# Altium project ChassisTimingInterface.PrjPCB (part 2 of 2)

## Sheet ChassisTimingInterface5.SchDoc
size C; SheetNumber: 5; SheetTotal: 6
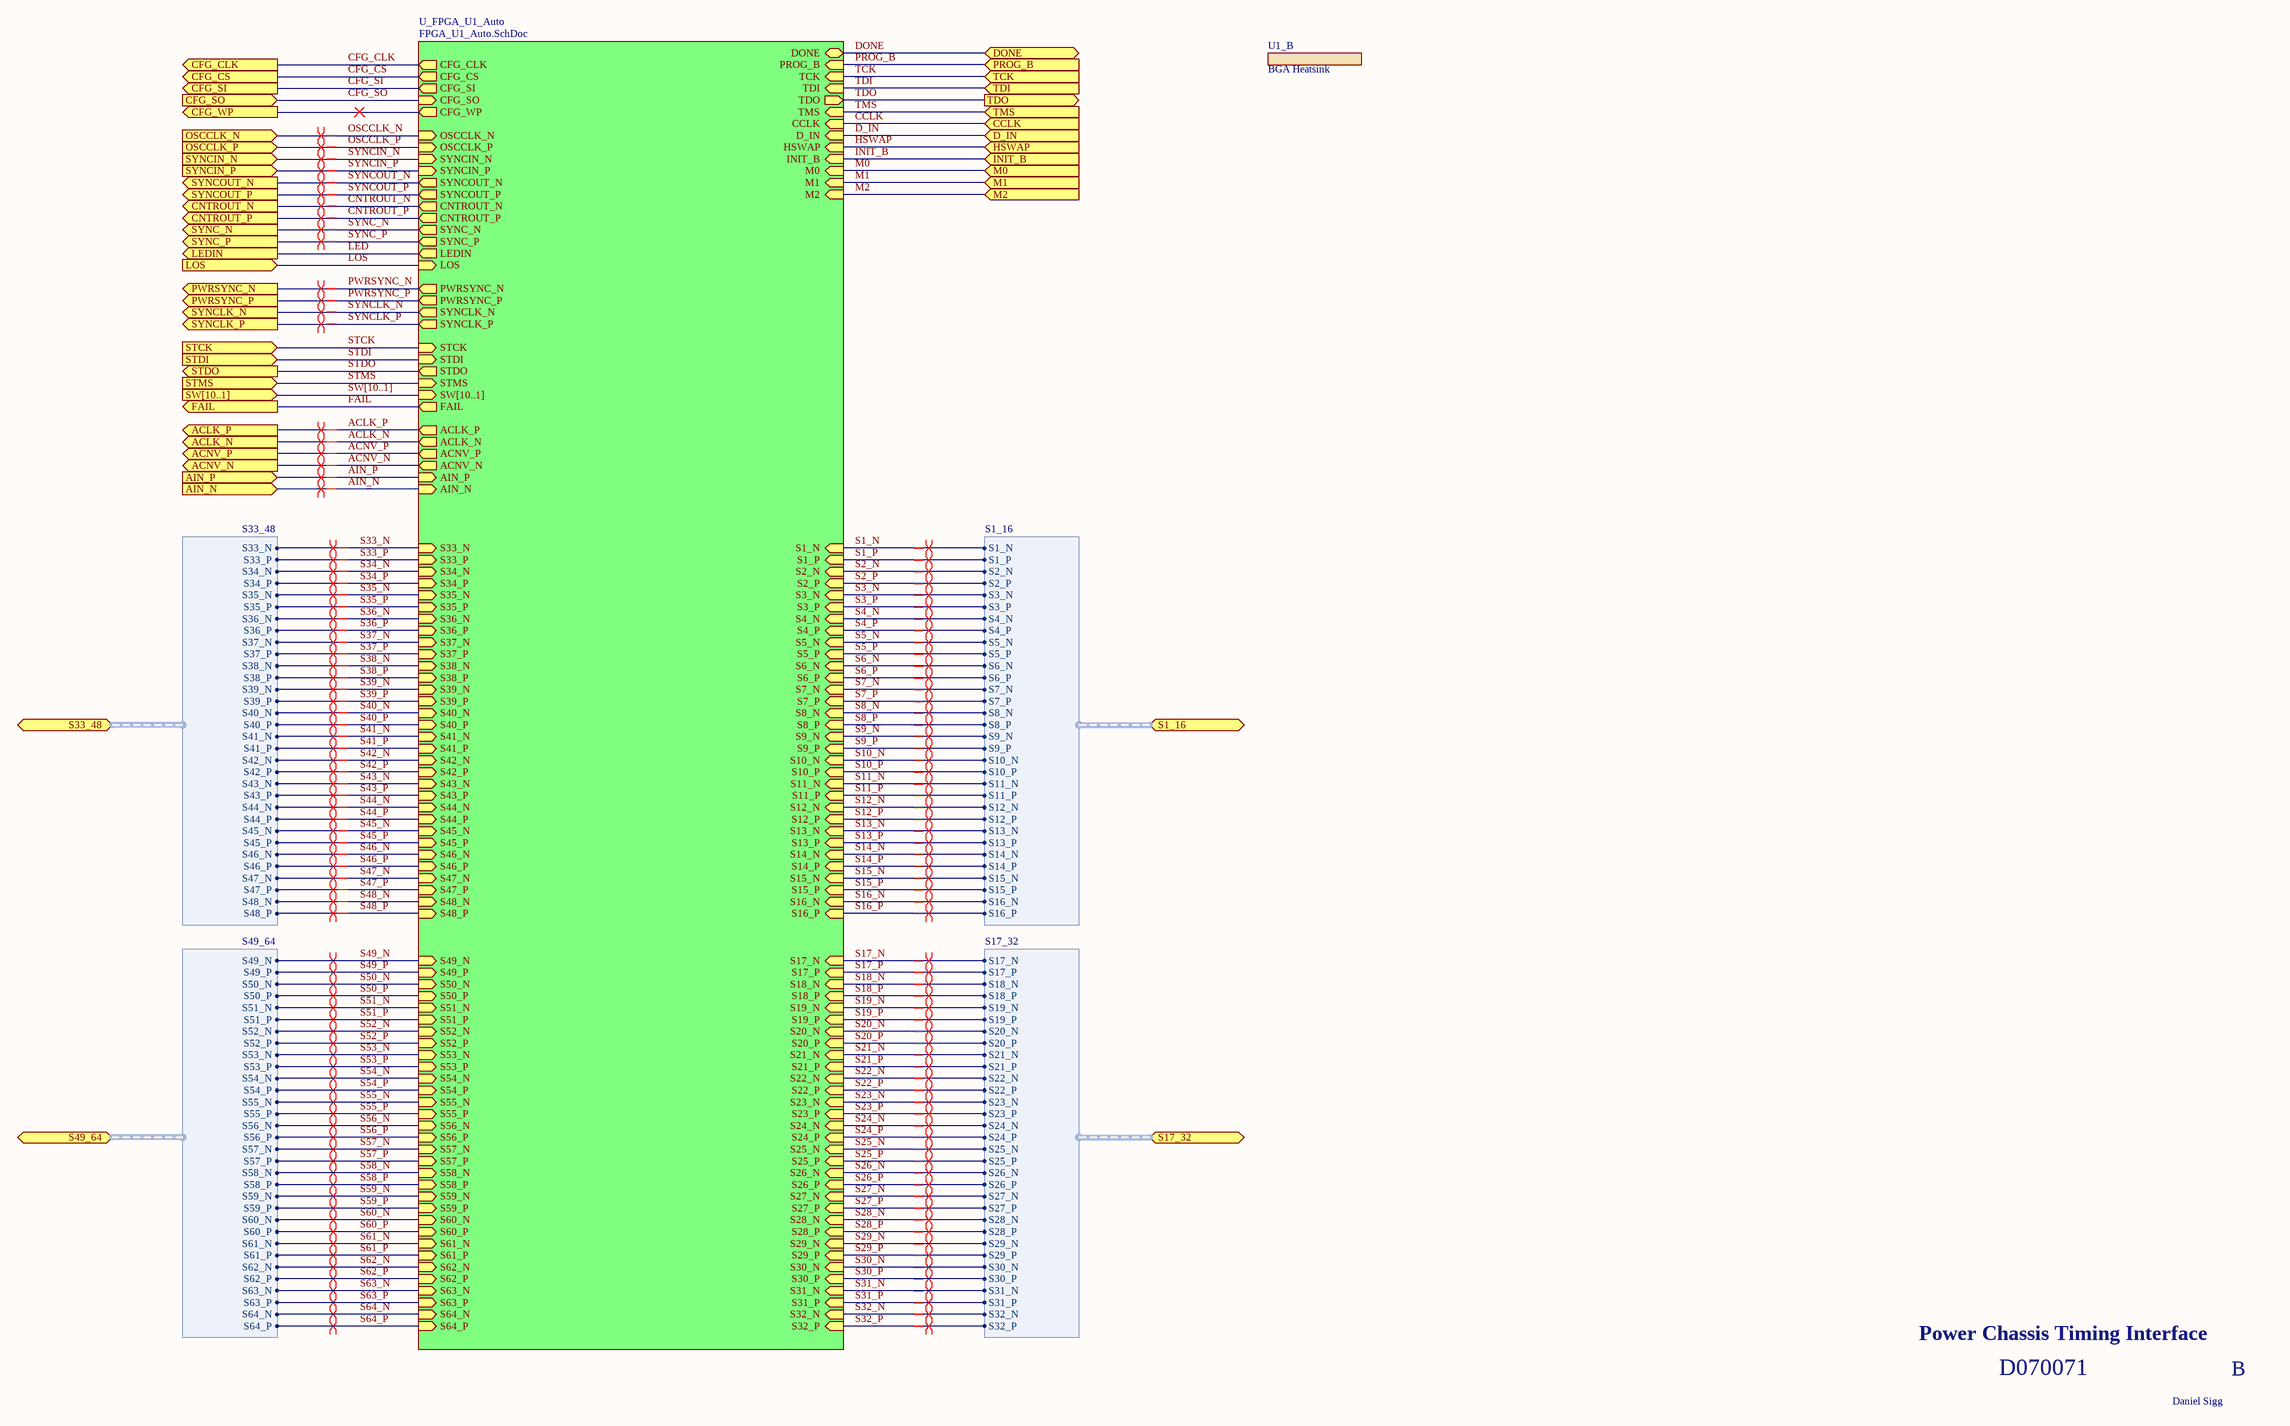
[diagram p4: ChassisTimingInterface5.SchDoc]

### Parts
U1_B  BGA Heatsink  (mechanical)

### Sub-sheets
U_FPGA_U1_Auto = FPGA_U1_Auto.SchDoc: CCLK (in), CFG_CLK (out), CFG_CS (out), CFG_SI (out), CFG_SO (in), CFG_WP (out), CNTROUT_N (out), CNTROUT_P (out), D_IN (in), HSWAP (in), INIT_B (in), LEDIN (out), LOS (in), M0 (in), M1 (in), M2 (in), OSCCLK_N (in), OSCCLK_P (in), PWRSYNC_N (out), PWRSYNC_P (out), S1_N (in), S1_P (in), S2_N (in), S2_P (in), S3_N (in), S3_P (in), S4_N (in), S4_P (in), S5_N (in), S5_P (in), S6_N (in), S6_P (in), S7_N (in), S7_P (in), S8_N (in), S8_P (in), STCK (in), STDI (in), STDO (out), STMS (in), SW[10..1] (in), SYNC_N (out), SYNC_P (out), SYNCIN_N (in), SYNCIN_P (in), SYNCLK_N (out), SYNCLK_P (out), SYNCOUT_N (out), SYNCOUT_P (out), DONE (bidir), PROG_B (in), TCK (in), TDI (in), TDO (out), TMS (in), FAIL (out), S9_P (in), S9_N (in), S10_P (in), S10_N (in), S11_P (in), S11_N (in), S12_P (in), S12_N (in), S13_P (in), S13_N (in), S14_P (in), S14_N (in), S15_P (in), S15_N (in), S16_P (in), S16_N (in), ACLK_N (out), ACLK_P (out), ACNV_N (out), ACNV_P (out), AIN_N (in), AIN_P (in), S17_N (in), S17_P (in), S18_N (in), S18_P (in), S19_N (in), S19_P (in), S20_N (in), S20_P (in), S21_N (in), S21_P (in), S22_N (in), S22_P (in), S23_N (in), S23_P (in), S24_N (in), S24_P (in), S25_N (in), S25_P (in), S26_N (in), S26_P (in), S27_N (in), S27_P (in), S28_N (in), S28_P (in), S29_N (in), S29_P (in), S30_N (in), S30_P (in), S31_N (in), S31_P (in), S32_N (in), S32_P (in), S33_N (in), S33_P (in), S34_N (in), S34_P (in), S35_N (in), S35_P (in), S36_N (in), S36_P (in), S37_N (in), S37_P (in), S38_N (in), S38_P (in), S39_N (in), S39_P (in), S40_N (in), S40_P (in), S49_N (in), S49_P (in), S50_N (in), S50_P (in), S51_N (in), S51_P (in), S52_N (in), S52_P (in), S53_N (in), S53_P (in), S54_N (in), S54_P (in), S55_N (in), S55_P (in), S56_N (in), S56_P (in), S57_N (in), S57_P (in), S58_N (in), S58_P (in), S59_N (in), S59_P (in), S60_N (in), S60_P (in), S61_N (in), S61_P (in), S62_N (in), S62_P (in), S63_N (in), S63_P (in), S64_N (in), S64_P (in), S42_N (in), S41_P (in), S42_P (in), S43_N (in), S43_P (in), S44_N (in), S44_P (in), S45_N (in), S45_P (in), S46_N (in), S46_P (in), S47_N (in), S47_P (in), S48_N (in), S48_P (in), S41_N (in)

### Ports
ACLK_N (out), ACLK_P (out), ACNV_N (out), ACNV_P (out), AIN_N (in), AIN_P (in), CCLK (in), CFG_CLK (out), CFG_CS (out), CFG_SI (out), CFG_SO (in), CFG_WP (out), CNTROUT_N (out), CNTROUT_P (out), D_IN (in), DONE (bidir), FAIL (out), HSWAP (in), INIT_B (in), LEDIN (out), LOS (in), M0 (in), M1 (in), M2 (in), OSCCLK_N (in), OSCCLK_P (in), PROG_B (in), PWRSYNC_N (out), PWRSYNC_P (out), S1_16 (harness S1_16), S17_32 (harness S17_32), S33_48 (harness S33_48), S49_64 (harness S49_64), STCK (in), STDI (in), STDO (out), STMS (in), SW[10..1] (in), SYNC_N (out), SYNC_P (out), SYNCIN_N (in), SYNCIN_P (in), SYNCLK_N (out), SYNCLK_P (out), SYNCOUT_N (out), SYNCOUT_P (out), TCK (in), TDI (in), TDO (out), TMS (in)

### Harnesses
S1_16: S1_N, S1_P, S2_N, S2_P, S3_N, S3_P, S4_N, S4_P, S5_N, S5_P, S6_N, S6_P, S7_N, S7_P, S8_N, S8_P, S9_N, S9_P, S10_N, S10_P, S11_N, S11_P, S12_N, S12_P, S13_N, S13_P, S14_N, S14_P, S15_N, S15_P, S16_N, S16_P
S17_32: S17_N, S17_P, S18_N, S18_P, S19_N, S19_P, S20_N, S20_P, S21_N, S21_P, S22_N, S22_P, S23_N, S23_P, S24_N, S24_P, S25_N, S25_P, S26_N, S26_P, S27_N, S27_P, S28_N, S28_P, S29_N, S29_P, S30_N, S30_P, S31_N, S31_P, S32_N, S32_P
S33_48: S33_N, S33_P, S34_N, S34_P, S35_N, S35_P, S36_N, S36_P, S37_N, S37_P, S38_N, S38_P, S39_N, S39_P, S40_N, S40_P, S41_N, S41_P, S42_N, S42_P, S43_N, S43_P, S44_N, S44_P, S45_N, S45_P, S46_N, S46_P, S47_N, S47_P, S48_N, S48_P
S49_64: S49_N, S49_P, S50_N, S50_P, S51_N, S51_P, S52_N, S52_P, S53_N, S53_P, S54_N, S54_P, S55_N, S55_P, S56_N, S56_P, S57_N, S57_P, S58_N, S58_P, S59_N, S59_P, S60_N, S60_P, S61_N, S61_P, S62_N, S62_P, S63_N, S63_P, S64_N, S64_P

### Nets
ACLK_N: port ACLK_N, sheet U_FPGA_U1_Auto/ACLK_N
ACLK_P: port ACLK_P, sheet U_FPGA_U1_Auto/ACLK_P
ACNV_N: port ACNV_N, sheet U_FPGA_U1_Auto/ACNV_N
ACNV_P: port ACNV_P, sheet U_FPGA_U1_Auto/ACNV_P
AIN_N: port AIN_N, sheet U_FPGA_U1_Auto/AIN_N
AIN_P: port AIN_P, sheet U_FPGA_U1_Auto/AIN_P
CCLK: port CCLK, sheet U_FPGA_U1_Auto/CCLK
CFG_CLK: port CFG_CLK, sheet U_FPGA_U1_Auto/CFG_CLK
CFG_CS: port CFG_CS, sheet U_FPGA_U1_Auto/CFG_CS
CFG_SI: port CFG_SI, sheet U_FPGA_U1_Auto/CFG_SI
CFG_SO: port CFG_SO, sheet U_FPGA_U1_Auto/CFG_SO
CNTROUT_N: port CNTROUT_N, sheet U_FPGA_U1_Auto/CNTROUT_N
CNTROUT_P: port CNTROUT_P, sheet U_FPGA_U1_Auto/CNTROUT_P
D_IN: port D_IN, sheet U_FPGA_U1_Auto/D_IN
DONE: port DONE, sheet U_FPGA_U1_Auto/DONE
FAIL: port FAIL, sheet U_FPGA_U1_Auto/FAIL
HSWAP: port HSWAP, sheet U_FPGA_U1_Auto/HSWAP
INIT_B: port INIT_B, sheet U_FPGA_U1_Auto/INIT_B
LED: port LEDIN, sheet U_FPGA_U1_Auto/LEDIN
LOS: port LOS, sheet U_FPGA_U1_Auto/LOS
M0: port M0, sheet U_FPGA_U1_Auto/M0
M1: port M1, sheet U_FPGA_U1_Auto/M1
M2: port M2, sheet U_FPGA_U1_Auto/M2
OSCCLK_N: port OSCCLK_N, sheet U_FPGA_U1_Auto/OSCCLK_N
OSCCLK_P: port OSCCLK_P, sheet U_FPGA_U1_Auto/OSCCLK_P
PROG_B: port PROG_B, sheet U_FPGA_U1_Auto/PROG_B
PWRSYNC_N: port PWRSYNC_N, sheet U_FPGA_U1_Auto/PWRSYNC_N
PWRSYNC_P: port PWRSYNC_P, sheet U_FPGA_U1_Auto/PWRSYNC_P
S1_N: sheet U_FPGA_U1_Auto/S1_N, port S1_16.S1_N  [project net S1_16.S1_N]
S1_P: sheet U_FPGA_U1_Auto/S1_P, port S1_16.S1_P  [project net S1_16.S1_P]
S2_N: sheet U_FPGA_U1_Auto/S2_N, port S1_16.S2_N  [project net S1_16.S2_N]
S2_P: sheet U_FPGA_U1_Auto/S2_P, port S1_16.S2_P  [project net S1_16.S2_P]
S3_N: sheet U_FPGA_U1_Auto/S3_N, port S1_16.S3_N  [project net S1_16.S3_N]
S3_P: sheet U_FPGA_U1_Auto/S3_P, port S1_16.S3_P  [project net S1_16.S3_P]
S4_N: sheet U_FPGA_U1_Auto/S4_N, port S1_16.S4_N  [project net S1_16.S4_N]
S4_P: sheet U_FPGA_U1_Auto/S4_P, port S1_16.S4_P  [project net S1_16.S4_P]
S5_N: sheet U_FPGA_U1_Auto/S5_N, port S1_16.S5_N  [project net S1_16.S5_N]
S5_P: sheet U_FPGA_U1_Auto/S5_P, port S1_16.S5_P  [project net S1_16.S5_P]
S6_N: sheet U_FPGA_U1_Auto/S6_N, port S1_16.S6_N  [project net S1_16.S6_N]
S6_P: sheet U_FPGA_U1_Auto/S6_P, port S1_16.S6_P  [project net S1_16.S6_P]
S7_N: sheet U_FPGA_U1_Auto/S7_N, port S1_16.S7_N  [project net S1_16.S7_N]
S7_P: sheet U_FPGA_U1_Auto/S7_P, port S1_16.S7_P  [project net S1_16.S7_P]
S8_N: sheet U_FPGA_U1_Auto/S8_N, port S1_16.S8_N  [project net S1_16.S8_N]
S8_P: sheet U_FPGA_U1_Auto/S8_P, port S1_16.S8_P  [project net S1_16.S8_P]
S9_N: sheet U_FPGA_U1_Auto/S9_N, port S1_16.S9_N  [project net S1_16.S9_N]
S9_P: sheet U_FPGA_U1_Auto/S9_P, port S1_16.S9_P  [project net S1_16.S9_P]
S10_N: sheet U_FPGA_U1_Auto/S10_N, port S1_16.S10_N
S10_P: sheet U_FPGA_U1_Auto/S10_P, port S1_16.S10_P
S11_N: sheet U_FPGA_U1_Auto/S11_N, port S1_16.S11_N
S11_P: sheet U_FPGA_U1_Auto/S11_P, port S1_16.S11_P
S12_N: sheet U_FPGA_U1_Auto/S12_N, port S1_16.S12_N
S12_P: sheet U_FPGA_U1_Auto/S12_P, port S1_16.S12_P
S13_N: sheet U_FPGA_U1_Auto/S13_N, port S1_16.S13_N
S13_P: sheet U_FPGA_U1_Auto/S13_P, port S1_16.S13_P
S14_N: sheet U_FPGA_U1_Auto/S14_N, port S1_16.S14_N
S14_P: sheet U_FPGA_U1_Auto/S14_P, port S1_16.S14_P
S15_N: sheet U_FPGA_U1_Auto/S15_N, port S1_16.S15_N
S15_P: sheet U_FPGA_U1_Auto/S15_P, port S1_16.S15_P
S16_N: sheet U_FPGA_U1_Auto/S16_N, port S1_16.S16_N
S16_P: sheet U_FPGA_U1_Auto/S16_P, port S1_16.S16_P
S17_N: sheet U_FPGA_U1_Auto/S17_N, port S17_32.S17_N  [project net S17_32.S17_N]
S17_P: sheet U_FPGA_U1_Auto/S17_P, port S17_32.S17_P  [project net S17_32.S17_P]
S18_N: sheet U_FPGA_U1_Auto/S18_N, port S17_32.S18_N  [project net S17_32.S18_N]
S18_P: sheet U_FPGA_U1_Auto/S18_P, port S17_32.S18_P  [project net S17_32.S18_P]
S19_N: sheet U_FPGA_U1_Auto/S19_N, port S17_32.S19_N  [project net S17_32.S19_N]
S19_P: sheet U_FPGA_U1_Auto/S19_P, port S17_32.S19_P  [project net S17_32.S19_P]
S20_N: sheet U_FPGA_U1_Auto/S20_N, port S17_32.S20_N  [project net S17_32.S20_N]
S20_P: sheet U_FPGA_U1_Auto/S20_P, port S17_32.S20_P  [project net S17_32.S20_P]
S21_N: sheet U_FPGA_U1_Auto/S21_N, port S17_32.S21_N  [project net S17_32.S21_N]
S21_P: sheet U_FPGA_U1_Auto/S21_P, port S17_32.S21_P  [project net S17_32.S21_P]
S22_N: sheet U_FPGA_U1_Auto/S22_N, port S17_32.S22_N  [project net S17_32.S22_N]
S22_P: sheet U_FPGA_U1_Auto/S22_P, port S17_32.S22_P  [project net S17_32.S22_P]
S23_N: sheet U_FPGA_U1_Auto/S23_N, port S17_32.S23_N  [project net S17_32.S23_N]
S23_P: sheet U_FPGA_U1_Auto/S23_P, port S17_32.S23_P  [project net S17_32.S23_P]
S24_N: sheet U_FPGA_U1_Auto/S24_N, port S17_32.S24_N  [project net S17_32.S24_N]
S24_P: sheet U_FPGA_U1_Auto/S24_P, port S17_32.S24_P  [project net S17_32.S24_P]
S25_N: sheet U_FPGA_U1_Auto/S25_N, port S17_32.S25_N  [project net S17_32.S25_N]
S25_P: sheet U_FPGA_U1_Auto/S25_P, port S17_32.S25_P  [project net S17_32.S25_P]
S26_N: sheet U_FPGA_U1_Auto/S26_N, port S17_32.S26_N  [project net S17_32.S26_N]
S26_P: sheet U_FPGA_U1_Auto/S26_P, port S17_32.S26_P  [project net S17_32.S26_P]
S27_N: sheet U_FPGA_U1_Auto/S27_N, port S17_32.S27_N  [project net S17_32.S27_N]
S27_P: sheet U_FPGA_U1_Auto/S27_P, port S17_32.S27_P  [project net S17_32.S27_P]
S28_N: sheet U_FPGA_U1_Auto/S28_N, port S17_32.S28_N  [project net S17_32.S28_N]
S28_P: sheet U_FPGA_U1_Auto/S28_P, port S17_32.S28_P  [project net S17_32.S28_P]
S29_N: sheet U_FPGA_U1_Auto/S29_N, port S17_32.S29_N  [project net S17_32.S29_N]
S29_P: sheet U_FPGA_U1_Auto/S29_P, port S17_32.S29_P  [project net S17_32.S29_P]
S30_N: sheet U_FPGA_U1_Auto/S30_N, port S17_32.S30_N  [project net S17_32.S30_N]
S30_P: sheet U_FPGA_U1_Auto/S30_P, port S17_32.S30_P  [project net S17_32.S30_P]
S31_N: sheet U_FPGA_U1_Auto/S31_N, port S17_32.S31_N  [project net S17_32.S31_N]
S31_P: sheet U_FPGA_U1_Auto/S31_P, port S17_32.S31_P  [project net S17_32.S31_P]
S32_N: sheet U_FPGA_U1_Auto/S32_N, port S17_32.S32_N  [project net S17_32.S32_N]
S32_P: sheet U_FPGA_U1_Auto/S32_P, port S17_32.S32_P  [project net S17_32.S32_P]
S33_N: sheet U_FPGA_U1_Auto/S33_N, port S33_48.S33_N  [project net S33_48.S33_N]
S33_P: sheet U_FPGA_U1_Auto/S33_P, port S33_48.S33_P  [project net S33_48.S33_P]
S34_N: sheet U_FPGA_U1_Auto/S34_N, port S33_48.S34_N  [project net S33_48.S34_N]
S34_P: sheet U_FPGA_U1_Auto/S34_P, port S33_48.S34_P  [project net S33_48.S34_P]
S35_N: sheet U_FPGA_U1_Auto/S35_N, port S33_48.S35_N  [project net S33_48.S35_N]
S35_P: sheet U_FPGA_U1_Auto/S35_P, port S33_48.S35_P  [project net S33_48.S35_P]
S36_N: sheet U_FPGA_U1_Auto/S36_N, port S33_48.S36_N  [project net S33_48.S36_N]
S36_P: sheet U_FPGA_U1_Auto/S36_P, port S33_48.S36_P  [project net S33_48.S36_P]
S37_N: sheet U_FPGA_U1_Auto/S37_N, port S33_48.S37_N  [project net S33_48.S37_N]
S37_P: sheet U_FPGA_U1_Auto/S37_P, port S33_48.S37_P  [project net S33_48.S37_P]
S38_N: sheet U_FPGA_U1_Auto/S38_N, port S33_48.S38_N  [project net S33_48.S38_N]
S38_P: sheet U_FPGA_U1_Auto/S38_P, port S33_48.S38_P  [project net S33_48.S38_P]
S39_N: sheet U_FPGA_U1_Auto/S39_N, port S33_48.S39_N  [project net S33_48.S39_N]
S39_P: sheet U_FPGA_U1_Auto/S39_P, port S33_48.S39_P  [project net S33_48.S39_P]
S40_N: sheet U_FPGA_U1_Auto/S40_N, port S33_48.S40_N  [project net S33_48.S40_N]
S40_P: sheet U_FPGA_U1_Auto/S40_P, port S33_48.S40_P  [project net S33_48.S40_P]
S41_N: sheet U_FPGA_U1_Auto/S41_N, port S33_48.S41_N  [project net S33_48.S41_N]
S41_P: sheet U_FPGA_U1_Auto/S41_P, port S33_48.S41_P  [project net S33_48.S41_P]
S42_N: sheet U_FPGA_U1_Auto/S42_N, port S33_48.S42_N  [project net S33_48.S42_N]
S42_P: sheet U_FPGA_U1_Auto/S42_P, port S33_48.S42_P  [project net S33_48.S42_P]
S43_N: sheet U_FPGA_U1_Auto/S43_N, port S33_48.S43_N  [project net S33_48.S43_N]
S43_P: sheet U_FPGA_U1_Auto/S43_P, port S33_48.S43_P  [project net S33_48.S43_P]
S44_N: sheet U_FPGA_U1_Auto/S44_N, port S33_48.S44_N  [project net S33_48.S44_N]
S44_P: sheet U_FPGA_U1_Auto/S44_P, port S33_48.S44_P  [project net S33_48.S44_P]
S45_N: sheet U_FPGA_U1_Auto/S45_N, port S33_48.S45_N  [project net S33_48.S45_N]
S45_P: sheet U_FPGA_U1_Auto/S45_P, port S33_48.S45_P  [project net S33_48.S45_P]
S46_N: sheet U_FPGA_U1_Auto/S46_N, port S33_48.S46_N  [project net S33_48.S46_N]
S46_P: sheet U_FPGA_U1_Auto/S46_P, port S33_48.S46_P  [project net S33_48.S46_P]
S47_N: sheet U_FPGA_U1_Auto/S47_N, port S33_48.S47_N  [project net S33_48.S47_N]
S47_P: sheet U_FPGA_U1_Auto/S47_P, port S33_48.S47_P  [project net S33_48.S47_P]
S48_N: sheet U_FPGA_U1_Auto/S48_N, port S33_48.S48_N  [project net S33_48.S48_N]
S48_P: sheet U_FPGA_U1_Auto/S48_P, port S33_48.S48_P  [project net S33_48.S48_P]
S49_N: sheet U_FPGA_U1_Auto/S49_N, port S49_64.S49_N  [project net S49_64.S49_N]
S49_P: sheet U_FPGA_U1_Auto/S49_P, port S49_64.S49_P  [project net S49_64.S49_P]
S50_N: sheet U_FPGA_U1_Auto/S50_N, port S49_64.S50_N  [project net S49_64.S50_N]
S50_P: sheet U_FPGA_U1_Auto/S50_P, port S49_64.S50_P  [project net S49_64.S50_P]
S51_N: sheet U_FPGA_U1_Auto/S51_N, port S49_64.S51_N  [project net S49_64.S51_N]
S51_P: sheet U_FPGA_U1_Auto/S51_P, port S49_64.S51_P  [project net S49_64.S51_P]
S52_N: sheet U_FPGA_U1_Auto/S52_N, port S49_64.S52_N  [project net S49_64.S52_N]
S52_P: sheet U_FPGA_U1_Auto/S52_P, port S49_64.S52_P  [project net S49_64.S52_P]
S53_N: sheet U_FPGA_U1_Auto/S53_N, port S49_64.S53_N  [project net S49_64.S53_N]
S53_P: sheet U_FPGA_U1_Auto/S53_P, port S49_64.S53_P  [project net S49_64.S53_P]
S54_N: sheet U_FPGA_U1_Auto/S54_N, port S49_64.S54_N  [project net S49_64.S54_N]
S54_P: sheet U_FPGA_U1_Auto/S54_P, port S49_64.S54_P  [project net S49_64.S54_P]
S55_N: sheet U_FPGA_U1_Auto/S55_N, port S49_64.S55_N  [project net S49_64.S55_N]
S55_P: sheet U_FPGA_U1_Auto/S55_P, port S49_64.S55_P  [project net S49_64.S55_P]
S56_N: sheet U_FPGA_U1_Auto/S56_N, port S49_64.S56_N  [project net S49_64.S56_N]
S56_P: sheet U_FPGA_U1_Auto/S56_P, port S49_64.S56_P  [project net S49_64.S56_P]
S57_N: sheet U_FPGA_U1_Auto/S57_N, port S49_64.S57_N  [project net S49_64.S57_N]
S57_P: sheet U_FPGA_U1_Auto/S57_P, port S49_64.S57_P  [project net S49_64.S57_P]
S58_N: sheet U_FPGA_U1_Auto/S58_N, port S49_64.S58_N  [project net S49_64.S58_N]
S58_P: sheet U_FPGA_U1_Auto/S58_P, port S49_64.S58_P  [project net S49_64.S58_P]
S59_N: sheet U_FPGA_U1_Auto/S59_N, port S49_64.S59_N  [project net S49_64.S59_N]
S59_P: sheet U_FPGA_U1_Auto/S59_P, port S49_64.S59_P  [project net S49_64.S59_P]
S60_N: sheet U_FPGA_U1_Auto/S60_N, port S49_64.S60_N  [project net S49_64.S60_N]
S60_P: sheet U_FPGA_U1_Auto/S60_P, port S49_64.S60_P  [project net S49_64.S60_P]
S61_N: sheet U_FPGA_U1_Auto/S61_N, port S49_64.S61_N  [project net S49_64.S61_N]
S61_P: sheet U_FPGA_U1_Auto/S61_P, port S49_64.S61_P  [project net S49_64.S61_P]
S62_N: sheet U_FPGA_U1_Auto/S62_N, port S49_64.S62_N  [project net S49_64.S62_N]
S62_P: sheet U_FPGA_U1_Auto/S62_P, port S49_64.S62_P  [project net S49_64.S62_P]
S63_N: sheet U_FPGA_U1_Auto/S63_N, port S49_64.S63_N  [project net S49_64.S63_N]
S63_P: sheet U_FPGA_U1_Auto/S63_P, port S49_64.S63_P  [project net S49_64.S63_P]
S64_N: sheet U_FPGA_U1_Auto/S64_N, port S49_64.S64_N  [project net S49_64.S64_N]
S64_P: sheet U_FPGA_U1_Auto/S64_P, port S49_64.S64_P  [project net S49_64.S64_P]
STCK: port STCK, sheet U_FPGA_U1_Auto/STCK
STDI: port STDI, sheet U_FPGA_U1_Auto/STDI
STDO: port STDO, sheet U_FPGA_U1_Auto/STDO
STMS: port STMS, sheet U_FPGA_U1_Auto/STMS
SYNC_N: port SYNC_N, sheet U_FPGA_U1_Auto/SYNC_N
SYNC_P: port SYNC_P, sheet U_FPGA_U1_Auto/SYNC_P
SYNCIN_N: port SYNCIN_N, sheet U_FPGA_U1_Auto/SYNCIN_N
SYNCIN_P: port SYNCIN_P, sheet U_FPGA_U1_Auto/SYNCIN_P
SYNCLK_N: port SYNCLK_N, sheet U_FPGA_U1_Auto/SYNCLK_N
SYNCLK_P: port SYNCLK_P, sheet U_FPGA_U1_Auto/SYNCLK_P
SYNCOUT_N: port SYNCOUT_N, sheet U_FPGA_U1_Auto/SYNCOUT_N
SYNCOUT_P: port SYNCOUT_P, sheet U_FPGA_U1_Auto/SYNCOUT_P
TCK: port TCK, sheet U_FPGA_U1_Auto/TCK
TDI: port TDI, sheet U_FPGA_U1_Auto/TDI  [project net TDI_B]
TDO: port TDO, sheet U_FPGA_U1_Auto/TDO
TMS: port TMS, sheet U_FPGA_U1_Auto/TMS
(unnamed): port CFG_WP, sheet U_FPGA_U1_Auto/CFG_WP

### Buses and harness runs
bus SW[10..1] = port SW[10..1] = sheet U_FPGA_U1_Auto/SW[10..1]

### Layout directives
differential pair: ACLK_N, ACLK_P, ACNV_N, ACNV_P, AIN_N, AIN_P, CNTROUT_N, CNTROUT_P, OSCCLK_N, OSCCLK_P, PWRSYNC_N, PWRSYNC_P, S1_16.S1_N, S1_16.S1_P, S1_16.S2_N, S1_16.S2_P, S1_16.S3_N, S1_16.S3_P, S1_16.S4_N, S1_16.S4_P, S1_16.S5_N, S1_16.S5_P, S1_16.S6_N, S1_16.S6_P, S1_16.S7_N, S1_16.S7_P, S1_16.S8_N, S1_16.S8_P, S1_16.S9_N, S1_16.S9_P, S10_N, S10_P, S11_N, S11_P, S12_N, S12_P, S13_N, S13_P, S14_N, S14_P, S15_N, S15_P, S16_N, S16_P, S17_32.S17_N, S17_32.S17_P, S17_32.S18_N, S17_32.S18_P, S17_32.S19_N, S17_32.S19_P, S17_32.S20_N, S17_32.S20_P, S17_32.S21_N, S17_32.S21_P, S17_32.S22_N, S17_32.S22_P, S17_32.S23_N, S17_32.S23_P, S17_32.S24_N, S17_32.S24_P, S17_32.S25_N, S17_32.S25_P, S17_32.S26_N, S17_32.S26_P, S17_32.S27_N, S17_32.S27_P, S17_32.S28_N, S17_32.S28_P, S17_32.S29_N, S17_32.S29_P, S17_32.S30_N, S17_32.S30_P, S17_32.S31_N, S17_32.S31_P, S17_32.S32_N, S17_32.S32_P, S33_48.S33_N, S33_48.S33_P, S33_48.S34_N, S33_48.S34_P, S33_48.S35_N, S33_48.S35_P, S33_48.S36_N, S33_48.S36_P, S33_48.S37_N, S33_48.S37_P, S33_48.S38_N, S33_48.S38_P, S33_48.S39_N, S33_48.S39_P, S33_48.S40_N, S33_48.S40_P, S33_48.S41_N, S33_48.S41_P, S33_48.S42_N, S33_48.S42_P, S33_48.S43_N, S33_48.S43_P, S33_48.S44_N, S33_48.S44_P, S33_48.S45_N, S33_48.S45_P, S33_48.S46_N, S33_48.S46_P, S33_48.S47_N, S33_48.S47_P, S33_48.S48_N, S33_48.S48_P, S49_64.S49_N, S49_64.S49_P, S49_64.S50_N, S49_64.S50_P, S49_64.S51_N, S49_64.S51_P, S49_64.S52_N, S49_64.S52_P, S49_64.S53_N, S49_64.S53_P, S49_64.S54_N, S49_64.S54_P, S49_64.S55_N, S49_64.S55_P, S49_64.S56_N, S49_64.S56_P, S49_64.S57_N, S49_64.S57_P, S49_64.S58_N, S49_64.S58_P, S49_64.S59_N, S49_64.S59_P, S49_64.S60_N, S49_64.S60_P, S49_64.S61_N, S49_64.S61_P, S49_64.S62_N, S49_64.S62_P, S49_64.S63_N, S49_64.S63_P, S49_64.S64_N, S49_64.S64_P, SYNC_N, SYNC_P, SYNCIN_N, SYNCIN_P, SYNCLK_N, SYNCLK_P, SYNCOUT_N, SYNCOUT_P

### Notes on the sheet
- Power Chassis Timing Interface
- D070071
- Daniel Sigg
- B

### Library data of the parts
U1_B = Partlist: Additional part number; Part Number: INM19001-23W/2.6 BU

## Sheet FPGA_U1_Auto.SchDoc: D070071
size C; Generated From FPGA Project: FPGAChassisTiming.PrjFpg; UNUSED_SPECIAL: NoERC; UNUSED_IO: NoERC; VREF: NoERC; UNUSED_INPUT: NoERC; SheetNumber: 6; SheetTotal: 6
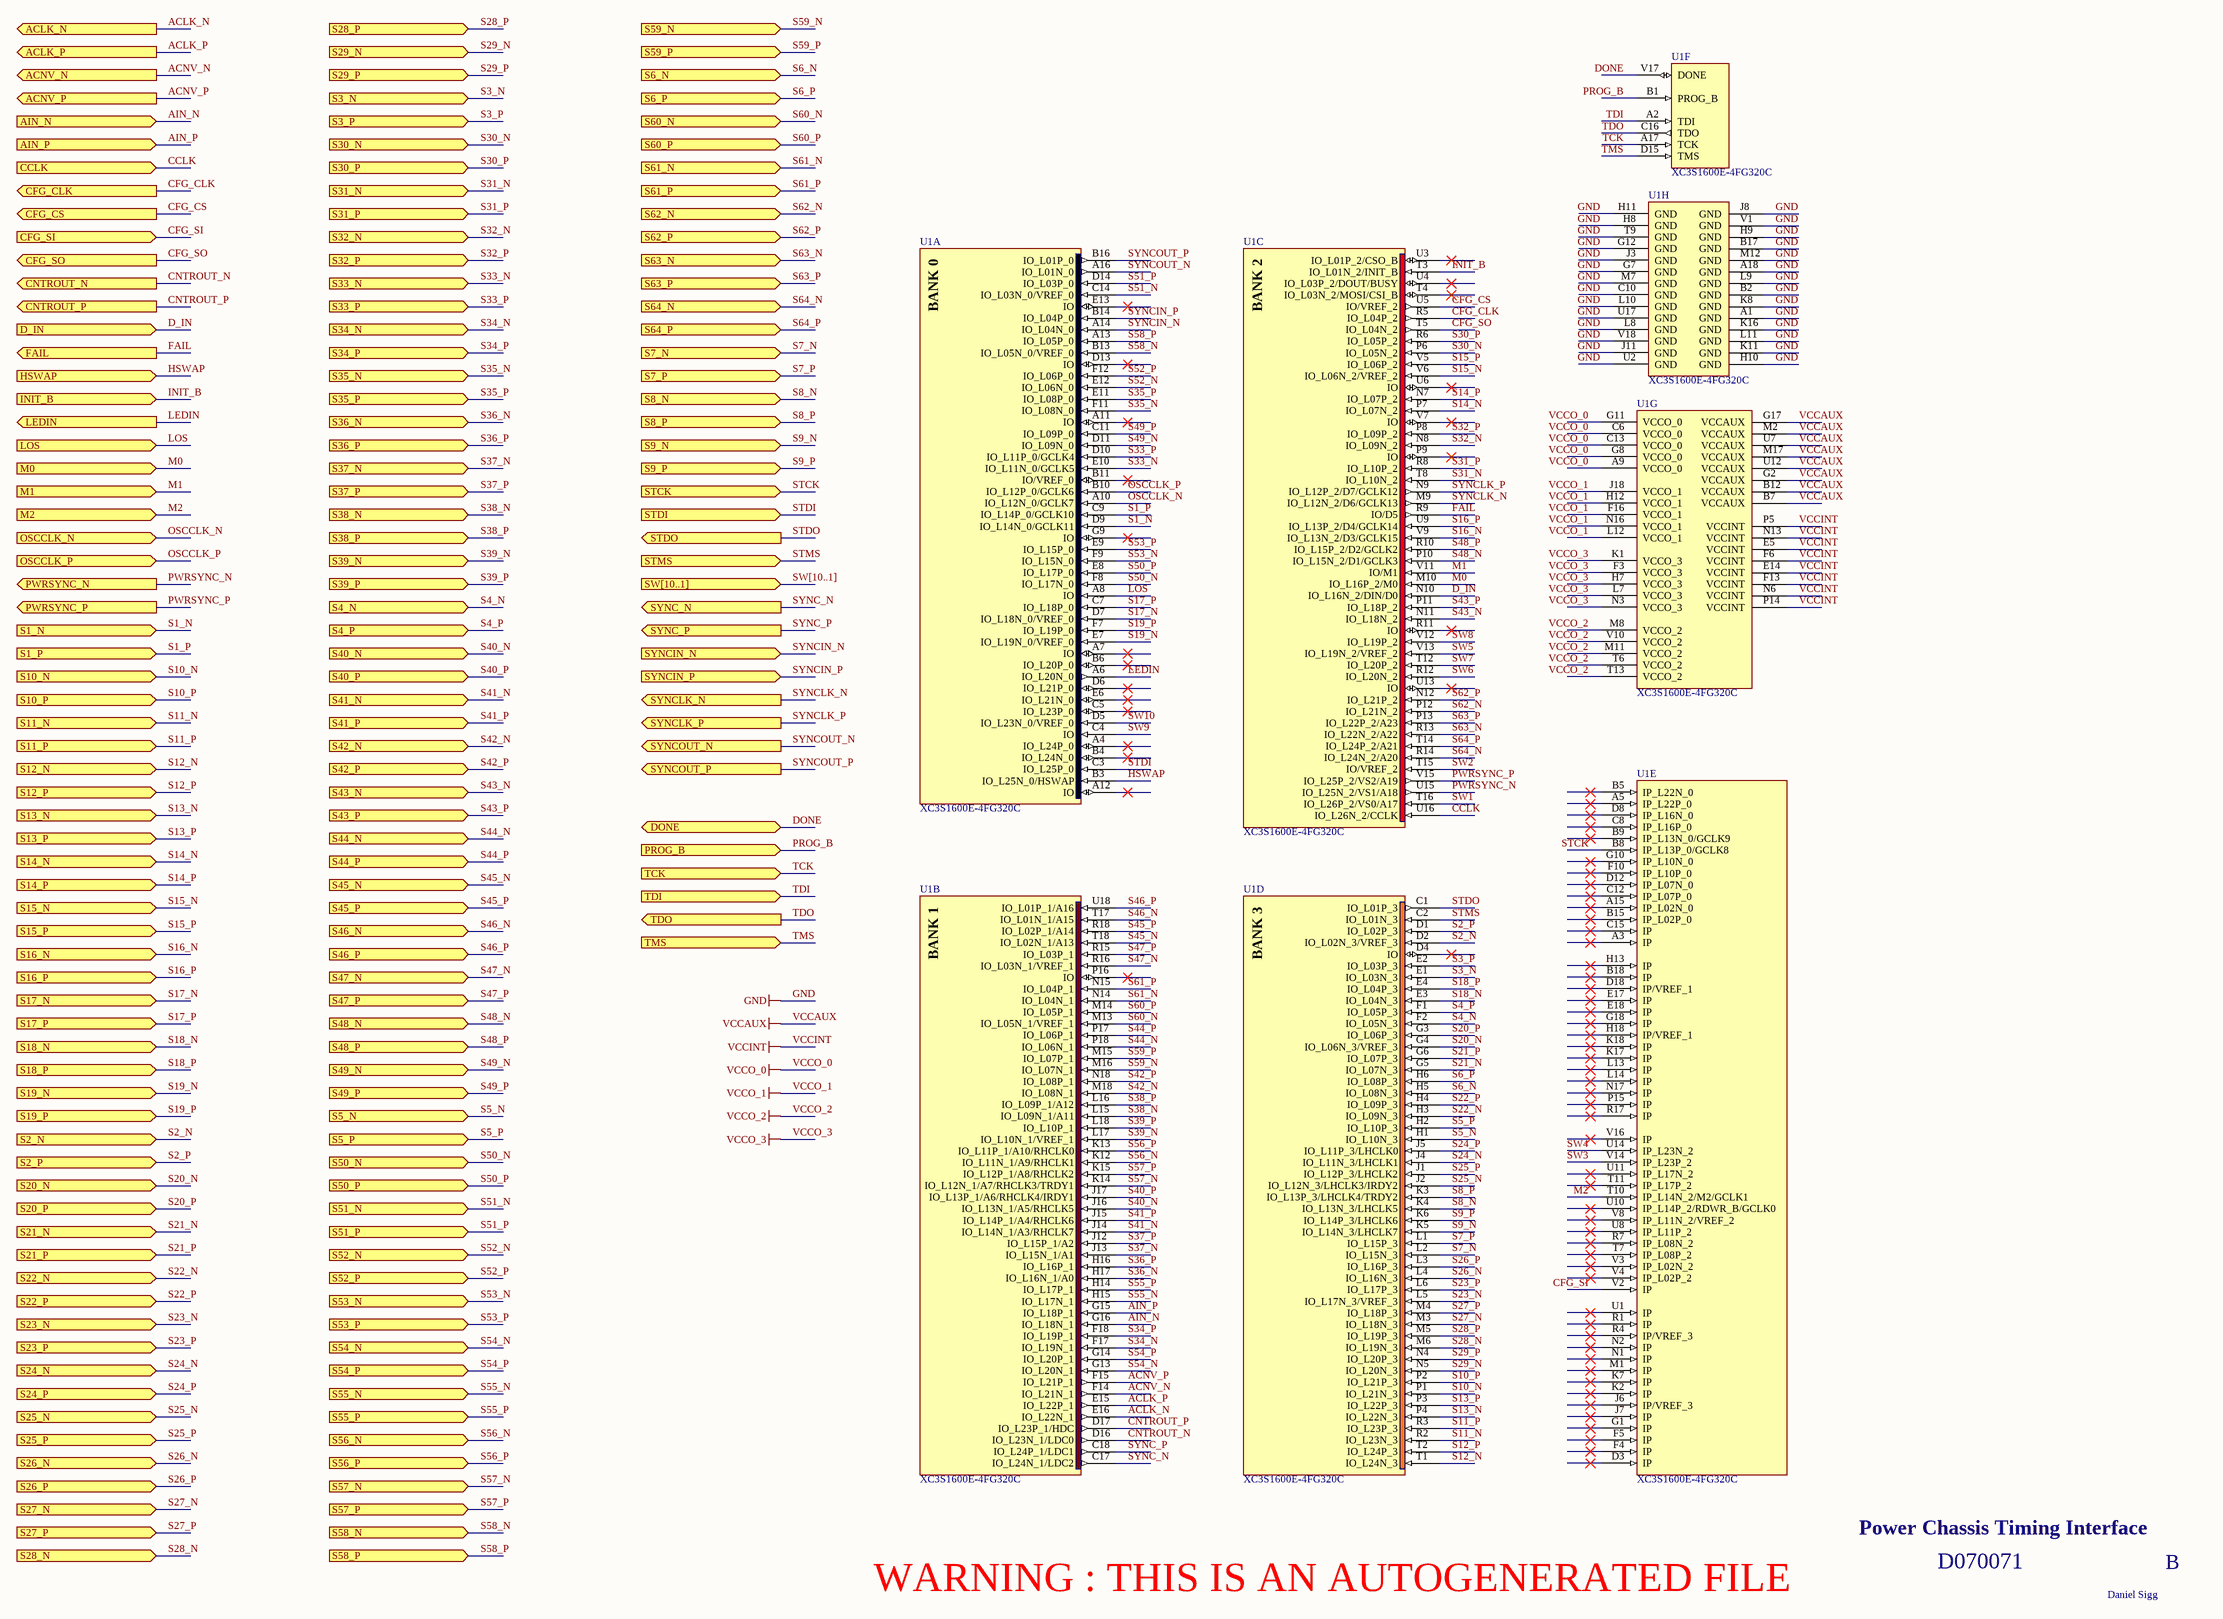
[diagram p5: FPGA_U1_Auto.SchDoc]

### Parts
U1  XC3S1600E-4FG320C  [FG320]  (parts A,B,C,D,E,F,G,H of 8)

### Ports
ACLK_N (out), ACLK_P (out), ACNV_N (out), ACNV_P (out), AIN_N (in), AIN_P (in), CCLK (in), CFG_CLK (out), CFG_CS (out), CFG_SI (in), CFG_SO (out), CNTROUT_N (out), CNTROUT_P (out), D_IN (in), DONE (bidir), FAIL (out), HSWAP (in), INIT_B (in), LEDIN (out), LOS (in), M0 (in), M1 (in), M2 (in), OSCCLK_N (in), OSCCLK_P (in), PROG_B (in), PWRSYNC_N (out), PWRSYNC_P (out), S1_N (in), S1_P (in), S2_N (in), S2_P (in), S3_N (in), S3_P (in), S4_N (in), S4_P (in), S5_N (in), S5_P (in), S6_N (in), S6_P (in), S7_N (in), S7_P (in), S8_N (in), S8_P (in), S9_N (in), S9_P (in), S10_N (in), S10_P (in), S11_N (in), S11_P (in), S12_N (in), S12_P (in), S13_N (in), S13_P (in), S14_N (in), S14_P (in), S15_N (in), S15_P (in), S16_N (in), S16_P (in), S17_N (in), S17_P (in), S18_N (in), S18_P (in), S19_N (in), S19_P (in), S20_N (in), S20_P (in), S21_N (in), S21_P (in), S22_N (in), S22_P (in), S23_N (in), S23_P (in), S24_N (in), S24_P (in), S25_N (in), S25_P (in), S26_N (in), S26_P (in), S27_N (in), S27_P (in), S28_N (in), S28_P (in), S29_N (in), S29_P (in), S30_N (in), S30_P (in), S31_N (in), S31_P (in), S32_N (in), S32_P (in), S33_N (in), S33_P (in), S34_N (in), S34_P (in), S35_N (in), S35_P (in), S36_N (in), S36_P (in), S37_N (in), S37_P (in), S38_N (in), S38_P (in), S39_N (in), S39_P (in), S40_N (in), S40_P (in), S41_N (in), S41_P (in), S42_N (in), S42_P (in), S43_N (in), S43_P (in), S44_N (in), S44_P (in), S45_N (in), S45_P (in), S46_N (in), S46_P (in), S47_N (in), S47_P (in), S48_N (in), S48_P (in), S49_N (in), S49_P (in), S50_N (in), S50_P (in), S51_N (in), S51_P (in), S52_N (in), S52_P (in), S53_N (in), S53_P (in), S54_N (in), S54_P (in), S55_N (in), S55_P (in), S56_N (in), S56_P (in), S57_N (in), S57_P (in), S58_N (in), S58_P (in), S59_N (in), S59_P (in), S60_N (in), S60_P (in), S61_N (in), S61_P (in), S62_N (in), S62_P (in), S63_N (in), S63_P (in), S64_N (in), S64_P (in), STCK (in), STDI (in), STDO (out), STMS (in), SW[10..1] (in), SYNC_N (out), SYNC_P (out), SYNCIN_N (in), SYNCIN_P (in), SYNCLK_N (out), SYNCLK_P (out), SYNCOUT_N (out), SYNCOUT_P (out), TCK (in), TDI (in), TDO (out), TMS (in)

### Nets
GND: U1.A1(GND) U1.A18(GND) U1.B2(GND) U1.B17(GND) U1.C10(GND) U1.G7(GND) U1.G12(GND) U1.H8(GND) U1.H9(GND) U1.H10(GND) U1.H11(GND) U1.J3(GND) U1.J8(GND) U1.J11(GND) U1.K8(GND) U1.K11(GND) U1.K16(GND) U1.L8(GND) U1.L9(GND) U1.L10(GND) U1.L11(GND) U1.M7(GND) U1.M12(GND) U1.T9(GND) U1.U2(GND) U1.U17(GND) U1.V1(GND) U1.V18(GND)
VCCAUX: U1.A9(VCCO_0) U1.B7(VCCAUX) U1.B12(VCCAUX) U1.C6(VCCO_0) U1.C13(VCCO_0) U1.F3(VCCO_3) U1.F16(VCCO_1) U1.G2(VCCAUX) U1.G8(VCCO_0) U1.G11(VCCO_0) U1.G17(VCCAUX) U1.H7(VCCO_3) U1.H12(VCCO_1) U1.J18(VCCO_1) U1.K1(VCCO_3) U1.L7(VCCO_3) U1.L12(VCCO_1) U1.M2(VCCAUX) U1.M8(VCCO_2) U1.M11(VCCO_2) U1.M17(VCCAUX) U1.N3(VCCO_3) U1.N16(VCCO_1) U1.T6(VCCO_2) U1.T13(VCCO_2) U1.U7(VCCAUX) U1.U12(VCCAUX) U1.V10(VCCO_2)  [also labelled VCCO_0, VCCO_1, VCCO_2, VCCO_3]
VCCINT: U1.E5(VCCINT) U1.E14(VCCINT) U1.F6(VCCINT) U1.F13(VCCINT) U1.N6(VCCINT) U1.N13(VCCINT) U1.P5(VCCINT) U1.P14(VCCINT)
ACLK_N: U1.E16(IO_L22N_1) ; port ACLK_N
ACLK_P: U1.E15(IO_L22P_1) ; port ACLK_P
ACNV_N: U1.F14(IO_L21N_1) ; port ACNV_N
ACNV_P: U1.F15(IO_L21P_1) ; port ACNV_P
AIN_N: U1.G16(IO_L18N_1) ; port AIN_N
AIN_P: U1.G15(IO_L18P_1) ; port AIN_P
CCLK: U1.U16(IO_L26N_2/CCLK) ; port CCLK
CFG_CLK: U1.R5(IO_L04P_2) ; port CFG_CLK
CFG_CS: U1.U5(IO/VREF_2) ; port CFG_CS
CFG_SI: U1.V2(IP) ; port CFG_SI
CFG_SO: U1.T5(IO_L04N_2) ; port CFG_SO
CNTROUT_N: U1.D16(IO_L23N_1/LDC0) ; port CNTROUT_N
CNTROUT_P: U1.D17(IO_L23P_1/HDC) ; port CNTROUT_P
D_IN: U1.N10(IO_L16N_2/DIN/D0) ; port D_IN
DONE: U1.V17(DONE) ; port DONE
FAIL: U1.R9(IO/D5) ; port FAIL
HSWAP: U1.B3(IO_L25N_0/HSWAP) ; port HSWAP
INIT_B: U1.T3(IO_L01N_2/INIT_B) ; port INIT_B
LEDIN: U1.A6(IO_L20N_0) ; port LEDIN  [project net LED]
LOS: U1.A8(IO) ; port LOS
M0: U1.M10(IO_L16P_2/M0) ; port M0
M1: U1.V11(IO/M1) ; port M1
M2: U1.T10(IP_L14N_2/M2/GCLK1) ; port M2
OSCCLK_N: U1.A10(IO_L12N_0/GCLK7) ; port OSCCLK_N
OSCCLK_P: U1.B10(IO_L12P_0/GCLK6) ; port OSCCLK_P
PROG_B: U1.B1(PROG_B) ; port PROG_B
PWRSYNC_N: U1.U15(IO_L25N_2/VS1/A18) ; port PWRSYNC_N
PWRSYNC_P: U1.V15(IO_L25P_2/VS2/A19) ; port PWRSYNC_P
S1_N: U1.D9(IO_L14N_0/GCLK11) ; port S1_N  [project net S1_16.S1_N]
S1_P: U1.C9(IO_L14P_0/GCLK10) ; port S1_P  [project net S1_16.S1_P]
S2_N: U1.D2(IO_L02N_3/VREF_3) ; port S2_N  [project net S1_16.S2_N]
S2_P: U1.D1(IO_L02P_3) ; port S2_P  [project net S1_16.S2_P]
S3_N: U1.E1(IO_L03N_3) ; port S3_N  [project net S1_16.S3_N]
S3_P: U1.E2(IO_L03P_3) ; port S3_P  [project net S1_16.S3_P]
S4_N: U1.F2(IO_L05N_3) ; port S4_N  [project net S1_16.S4_N]
S4_P: U1.F1(IO_L05P_3) ; port S4_P  [project net S1_16.S4_P]
S5_N: U1.H1(IO_L10N_3) ; port S5_N  [project net S1_16.S5_N]
S5_P: U1.H2(IO_L10P_3) ; port S5_P  [project net S1_16.S5_P]
S6_N: U1.H5(IO_L08N_3) ; port S6_N  [project net S1_16.S6_N]
S6_P: U1.H6(IO_L08P_3) ; port S6_P  [project net S1_16.S6_P]
S7_N: U1.L2(IO_L15N_3) ; port S7_N  [project net S1_16.S7_N]
S7_P: U1.L1(IO_L15P_3) ; port S7_P  [project net S1_16.S7_P]
S8_N: U1.K4(IO_L13N_3/LHCLK5) ; port S8_N  [project net S1_16.S8_N]
S8_P: U1.K3(IO_L13P_3/LHCLK4/TRDY2) ; port S8_P  [project net S1_16.S8_P]
S9_N: U1.K5(IO_L14N_3/LHCLK7) ; port S9_N  [project net S1_16.S9_N]
S9_P: U1.K6(IO_L14P_3/LHCLK6) ; port S9_P  [project net S1_16.S9_P]
S10_N: U1.P1(IO_L21N_3) ; port S10_N
S10_P: U1.P2(IO_L21P_3) ; port S10_P
S11_N: U1.R2(IO_L23N_3) ; port S11_N
S11_P: U1.R3(IO_L23P_3) ; port S11_P
S12_N: U1.T1(IO_L24N_3) ; port S12_N
S12_P: U1.T2(IO_L24P_3) ; port S12_P
S13_N: U1.P4(IO_L22N_3) ; port S13_N
S13_P: U1.P3(IO_L22P_3) ; port S13_P
S14_N: U1.P7(IO_L07N_2) ; port S14_N
S14_P: U1.N7(IO_L07P_2) ; port S14_P
S15_N: U1.V6(IO_L06N_2/VREF_2) ; port S15_N
S15_P: U1.V5(IO_L06P_2) ; port S15_P
S16_N: U1.V9(IO_L13N_2/D3/GCLK15) ; port S16_N
S16_P: U1.U9(IO_L13P_2/D4/GCLK14) ; port S16_P
S17_N: U1.D7(IO_L18N_0/VREF_0) ; port S17_N  [project net S17_32.S17_N]
S17_P: U1.C7(IO_L18P_0) ; port S17_P  [project net S17_32.S17_P]
S18_N: U1.E3(IO_L04N_3) ; port S18_N  [project net S17_32.S18_N]
S18_P: U1.E4(IO_L04P_3) ; port S18_P  [project net S17_32.S18_P]
S19_N: U1.E7(IO_L19N_0/VREF_0) ; port S19_N  [project net S17_32.S19_N]
S19_P: U1.F7(IO_L19P_0) ; port S19_P  [project net S17_32.S19_P]
S20_N: U1.G4(IO_L06N_3/VREF_3) ; port S20_N  [project net S17_32.S20_N]
S20_P: U1.G3(IO_L06P_3) ; port S20_P  [project net S17_32.S20_P]
S21_N: U1.G5(IO_L07N_3) ; port S21_N  [project net S17_32.S21_N]
S21_P: U1.G6(IO_L07P_3) ; port S21_P  [project net S17_32.S21_P]
S22_N: U1.H3(IO_L09N_3) ; port S22_N  [project net S17_32.S22_N]
S22_P: U1.H4(IO_L09P_3) ; port S22_P  [project net S17_32.S22_P]
S23_N: U1.L5(IO_L17N_3/VREF_3) ; port S23_N  [project net S17_32.S23_N]
S23_P: U1.L6(IO_L17P_3) ; port S23_P  [project net S17_32.S23_P]
S24_N: U1.J4(IO_L11N_3/LHCLK1) ; port S24_N  [project net S17_32.S24_N]
S24_P: U1.J5(IO_L11P_3/LHCLK0) ; port S24_P  [project net S17_32.S24_P]
S25_N: U1.J2(IO_L12N_3/LHCLK3/IRDY2) ; port S25_N  [project net S17_32.S25_N]
S25_P: U1.J1(IO_L12P_3/LHCLK2) ; port S25_P  [project net S17_32.S25_P]
S26_N: U1.L4(IO_L16N_3) ; port S26_N  [project net S17_32.S26_N]
S26_P: U1.L3(IO_L16P_3) ; port S26_P  [project net S17_32.S26_P]
S27_N: U1.M3(IO_L18N_3) ; port S27_N  [project net S17_32.S27_N]
S27_P: U1.M4(IO_L18P_3) ; port S27_P  [project net S17_32.S27_P]
S28_N: U1.M6(IO_L19N_3) ; port S28_N  [project net S17_32.S28_N]
S28_P: U1.M5(IO_L19P_3) ; port S28_P  [project net S17_32.S28_P]
S29_N: U1.N5(IO_L20N_3) ; port S29_N  [project net S17_32.S29_N]
S29_P: U1.N4(IO_L20P_3) ; port S29_P  [project net S17_32.S29_P]
S30_N: U1.P6(IO_L05N_2) ; port S30_N  [project net S17_32.S30_N]
S30_P: U1.R6(IO_L05P_2) ; port S30_P  [project net S17_32.S30_P]
S31_N: U1.T8(IO_L10N_2) ; port S31_N  [project net S17_32.S31_N]
S31_P: U1.R8(IO_L10P_2) ; port S31_P  [project net S17_32.S31_P]
S32_N: U1.N8(IO_L09N_2) ; port S32_N  [project net S17_32.S32_N]
S32_P: U1.P8(IO_L09P_2) ; port S32_P  [project net S17_32.S32_P]
S33_N: U1.E10(IO_L11N_0/GCLK5) ; port S33_N  [project net S33_48.S33_N]
S33_P: U1.D10(IO_L11P_0/GCLK4) ; port S33_P  [project net S33_48.S33_P]
S34_N: U1.F17(IO_L19N_1) ; port S34_N  [project net S33_48.S34_N]
S34_P: U1.F18(IO_L19P_1) ; port S34_P  [project net S33_48.S34_P]
S35_N: U1.F11(IO_L08N_0) ; port S35_N  [project net S33_48.S35_N]
S35_P: U1.E11(IO_L08P_0) ; port S35_P  [project net S33_48.S35_P]
S36_N: U1.H17(IO_L16N_1/A0) ; port S36_N  [project net S33_48.S36_N]
S36_P: U1.H16(IO_L16P_1) ; port S36_P  [project net S33_48.S36_P]
S37_N: U1.J13(IO_L15N_1/A1) ; port S37_N  [project net S33_48.S37_N]
S37_P: U1.J12(IO_L15P_1/A2) ; port S37_P  [project net S33_48.S37_P]
S38_N: U1.L15(IO_L09N_1/A11) ; port S38_N  [project net S33_48.S38_N]
S38_P: U1.L16(IO_L09P_1/A12) ; port S38_P  [project net S33_48.S38_P]
S39_N: U1.L17(IO_L10N_1/VREF_1) ; port S39_N  [project net S33_48.S39_N]
S39_P: U1.L18(IO_L10P_1) ; port S39_P  [project net S33_48.S39_P]
S40_N: U1.J16(IO_L13N_1/A5/RHCLK5) ; port S40_N  [project net S33_48.S40_N]
S40_P: U1.J17(IO_L13P_1/A6/RHCLK4/IRDY1) ; port S40_P  [project net S33_48.S40_P]
S41_N: U1.J14(IO_L14N_1/A3/RHCLK7) ; port S41_N  [project net S33_48.S41_N]
S41_P: U1.J15(IO_L14P_1/A4/RHCLK6) ; port S41_P  [project net S33_48.S41_P]
S42_N: U1.M18(IO_L08N_1) ; port S42_N  [project net S33_48.S42_N]
S42_P: U1.N18(IO_L08P_1) ; port S42_P  [project net S33_48.S42_P]
S43_N: U1.N11(IO_L18N_2) ; port S43_N  [project net S33_48.S43_N]
S43_P: U1.P11(IO_L18P_2) ; port S43_P  [project net S33_48.S43_P]
S44_N: U1.P18(IO_L06N_1) ; port S44_N  [project net S33_48.S44_N]
S44_P: U1.P17(IO_L06P_1) ; port S44_P  [project net S33_48.S44_P]
S45_N: U1.T18(IO_L02N_1/A13) ; port S45_N  [project net S33_48.S45_N]
S45_P: U1.R18(IO_L02P_1/A14) ; port S45_P  [project net S33_48.S45_P]
S46_N: U1.T17(IO_L01N_1/A15) ; port S46_N  [project net S33_48.S46_N]
S46_P: U1.U18(IO_L01P_1/A16) ; port S46_P  [project net S33_48.S46_P]
S47_N: U1.R16(IO_L03N_1/VREF_1) ; port S47_N  [project net S33_48.S47_N]
S47_P: U1.R15(IO_L03P_1) ; port S47_P  [project net S33_48.S47_P]
S48_N: U1.P10(IO_L15N_2/D1/GCLK3) ; port S48_N  [project net S33_48.S48_N]
S48_P: U1.R10(IO_L15P_2/D2/GCLK2) ; port S48_P  [project net S33_48.S48_P]
S49_N: U1.D11(IO_L09N_0) ; port S49_N  [project net S49_64.S49_N]
S49_P: U1.C11(IO_L09P_0) ; port S49_P  [project net S49_64.S49_P]
S50_N: U1.F8(IO_L17N_0) ; port S50_N  [project net S49_64.S50_N]
S50_P: U1.E8(IO_L17P_0) ; port S50_P  [project net S49_64.S50_P]
S51_N: U1.C14(IO_L03N_0/VREF_0) ; port S51_N  [project net S49_64.S51_N]
S51_P: U1.D14(IO_L03P_0) ; port S51_P  [project net S49_64.S51_P]
S52_N: U1.E12(IO_L06N_0) ; port S52_N  [project net S49_64.S52_N]
S52_P: U1.F12(IO_L06P_0) ; port S52_P  [project net S49_64.S52_P]
S53_N: U1.F9(IO_L15N_0) ; port S53_N  [project net S49_64.S53_N]
S53_P: U1.E9(IO_L15P_0) ; port S53_P  [project net S49_64.S53_P]
S54_N: U1.G13(IO_L20N_1) ; port S54_N  [project net S49_64.S54_N]
S54_P: U1.G14(IO_L20P_1) ; port S54_P  [project net S49_64.S54_P]
S55_N: U1.H15(IO_L17N_1) ; port S55_N  [project net S49_64.S55_N]
S55_P: U1.H14(IO_L17P_1) ; port S55_P  [project net S49_64.S55_P]
S56_N: U1.K12(IO_L11N_1/A9/RHCLK1) ; port S56_N  [project net S49_64.S56_N]
S56_P: U1.K13(IO_L11P_1/A10/RHCLK0) ; port S56_P  [project net S49_64.S56_P]
S57_N: U1.K14(IO_L12N_1/A7/RHCLK3/TRDY1) ; port S57_N  [project net S49_64.S57_N]
S57_P: U1.K15(IO_L12P_1/A8/RHCLK2) ; port S57_P  [project net S49_64.S57_P]
S58_N: U1.B13(IO_L05N_0/VREF_0) ; port S58_N  [project net S49_64.S58_N]
S58_P: U1.A13(IO_L05P_0) ; port S58_P  [project net S49_64.S58_P]
S59_N: U1.M16(IO_L07N_1) ; port S59_N  [project net S49_64.S59_N]
S59_P: U1.M15(IO_L07P_1) ; port S59_P  [project net S49_64.S59_P]
S60_N: U1.M13(IO_L05N_1/VREF_1) ; port S60_N  [project net S49_64.S60_N]
S60_P: U1.M14(IO_L05P_1) ; port S60_P  [project net S49_64.S60_P]
S61_N: U1.N14(IO_L04N_1) ; port S61_N  [project net S49_64.S61_N]
S61_P: U1.N15(IO_L04P_1) ; port S61_P  [project net S49_64.S61_P]
S62_N: U1.P12(IO_L21N_2) ; port S62_N  [project net S49_64.S62_N]
S62_P: U1.N12(IO_L21P_2) ; port S62_P  [project net S49_64.S62_P]
S63_N: U1.R13(IO_L22N_2/A22) ; port S63_N  [project net S49_64.S63_N]
S63_P: U1.P13(IO_L22P_2/A23) ; port S63_P  [project net S49_64.S63_P]
S64_N: U1.R14(IO_L24N_2/A20) ; port S64_N  [project net S49_64.S64_N]
S64_P: U1.T14(IO_L24P_2/A21) ; port S64_P  [project net S49_64.S64_P]
STCK: U1.B8(IP_L13P_0/GCLK8) ; port STCK
STDI: U1.C3(IO_L25P_0) ; port STDI
STDO: U1.C1(IO_L01P_3) ; port STDO
STMS: U1.C2(IO_L01N_3) ; port STMS
SW1: U1.T16(IO_L26P_2/VS0/A17)
SW2: U1.T15(IO/VREF_2)
SW3: U1.V14(IP_L23P_2)
SW4: U1.U14(IP_L23N_2)
SW5: U1.V13(IO_L19N_2/VREF_2)
SW6: U1.R12(IO_L20N_2)
SW7: U1.T12(IO_L20P_2)
SW8: U1.V12(IO_L19P_2)
SW9: U1.C4(IO)
SW10: U1.D5(IO_L23N_0/VREF_0)
SYNC_N: U1.C17(IO_L24N_1/LDC2) ; port SYNC_N
SYNC_P: U1.C18(IO_L24P_1/LDC1) ; port SYNC_P
SYNCIN_N: U1.A14(IO_L04N_0) ; port SYNCIN_N
SYNCIN_P: U1.B14(IO_L04P_0) ; port SYNCIN_P
SYNCLK_N: U1.M9(IO_L12N_2/D6/GCLK13) ; port SYNCLK_N
SYNCLK_P: U1.N9(IO_L12P_2/D7/GCLK12) ; port SYNCLK_P
SYNCOUT_N: U1.A16(IO_L01N_0) ; port SYNCOUT_N
SYNCOUT_P: U1.B16(IO_L01P_0) ; port SYNCOUT_P
TCK: U1.A17(TCK) ; port TCK
TDI: U1.A2(TDI) ; port TDI  [project net TDI_B]
TDO: U1.C16(TDO) ; port TDO
TMS: U1.D15(TMS) ; port TMS

Not connected (* = marked no-connect by the designer): U1 A3(IP)* A4(IO_L24P_0)* A5(IP_L22P_0)* A7(IO)* A11(IO)* A12(IO)* A15(IP_L02N_0)* B4(IO_L24N_0)* B5(IP_L22N_0)* B6(IO_L20P_0)* B9(IP_L13N_0/GCLK9)* B11(IO/VREF_0)* B15(IP_L02P_0)* B18(IP)* C5(IO_L23P_0)* C8(IP_L16P_0)* C12(IP_L07P_0)* C15(IP)* D3(IP)* D4(IO)* D6(IO_L21P_0)* D8(IP_L16N_0)* D12(IP_L07N_0)* D13(IO)* D18(IP/VREF_1)* E6(IO_L21N_0)* E13(IO)* E17(IP)* E18(IP)* F4(IP)* F5(IP)* F10(IP_L10P_0)* G1(IP)* G9(IO)* G10(IP_L10N_0)* G18(IP)* H13(IP)* H18(IP/VREF_1)* J6(IP/VREF_3)* J7(IP)* K2(IP)* K7(IP)* K17(IP)* K18(IP)* L13(IP)* L14(IP)* M1(IP)* N1(IP)* N2(IP)* N17(IP)* P9(IO)* P15(IP)* P16(IO)* R1(IP)* R4(IP/VREF_3)* R7(IP_L08N_2)* R11(IO)* R17(IP)* T4(IO_L03N_2/MOSI/CSI_B)* T7(IP_L08P_2)* T11(IP_L17P_2)* U1(IP)* U3(IO_L01P_2/CSO_B)* U4(IO_L03P_2/DOUT/BUSY)* U6(IO)* U8(IP_L11P_2)* U10(IP_L14P_2/RDWR_B/GCLK0)* U11(IP_L17N_2)* U13(IO)* V3(IP_L02N_2)* V4(IP_L02P_2)* V7(IO)* V8(IP_L11N_2/VREF_2)* V16(IP)*

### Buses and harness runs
bus SW[10..1] = port SW[10..1]

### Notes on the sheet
- Power Chassis Timing Interface
- WARNING : THIS IS AN AUTOGENERATED FILE
- D070071
- Daniel Sigg
- B

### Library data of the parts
U1 = XC3S1600E-4FG320C: Spartan-3E 1.2V FPGA, 250 User I/Os, 320-Ball FBGA, Standard Performance, Commercial Grade; Part Number: 122-1481-ND

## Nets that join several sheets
12V: ChassisTimingInterface1 (P2.77 P2.79), ChassisTimingInterface4 (13 pins)
AGND: ChassisTimingInterface2 (21 pins), ChassisTimingInterface4 (C61.2)
GND: ChassisTimingInterface1 (39 pins), ChassisTimingInterface2 (36 pins), ChassisTimingInterface4 (112 pins), ChassisTimingInterface3 (44 pins), FPGA_U1_Auto (28 pins)
P10V: ChassisTimingInterface2 (6 pins), ChassisTimingInterface4 (5 pins)
P12V: ChassisTimingInterface1 (R2.2), ChassisTimingInterface4 (C48.2 L3.1 P7.1)
VCCAUX: ChassisTimingInterface1 (6 pins), ChassisTimingInterface2 (R6.5 R6.6 R6.7 R6.8), ChassisTimingInterface4 (58 pins), ChassisTimingInterface3 (24 pins), FPGA_U1_Auto (28 pins)
VCCConf: ChassisTimingInterface4 (6 pins), ChassisTimingInterface3 (6 pins)
VCCINT: ChassisTimingInterface4 (23 pins), FPGA_U1_Auto (8 pins)
VDD: ChassisTimingInterface1 (6 pins), ChassisTimingInterface2 (25 pins), ChassisTimingInterface4 (20 pins), ChassisTimingInterface3 (R28.1)
ACLK_N: ChassisTimingInterface2 (U6.6), FPGA_U1_Auto (U1.E16)
ACLK_P: ChassisTimingInterface2 (U6.5), FPGA_U1_Auto (U1.E15)
ACNV_N: ChassisTimingInterface2 (U6.8), FPGA_U1_Auto (U1.F14)
ACNV_P: ChassisTimingInterface2 (U6.7), FPGA_U1_Auto (U1.F15)
AIN_N: ChassisTimingInterface2 (U6.10), FPGA_U1_Auto (U1.G16)
AIN_P: ChassisTimingInterface2 (U6.9), FPGA_U1_Auto (U1.G15)
CCLK: ChassisTimingInterface3 (R29.2 R30.1 U13.12), FPGA_U1_Auto (U1.U16)
CFG_CLK: ChassisTimingInterface1 (P1.79), FPGA_U1_Auto (U1.R5)
CFG_CS: ChassisTimingInterface1 (P1.80), FPGA_U1_Auto (U1.U5)
CFG_SI: ChassisTimingInterface1 (P1.77), FPGA_U1_Auto (U1.V2)
CFG_SO: ChassisTimingInterface1 (P1.78), FPGA_U1_Auto (U1.T5)
CNTROUT_N: ChassisTimingInterface2 (U6.4), FPGA_U1_Auto (U1.D16)
CNTROUT_P: ChassisTimingInterface2 (U6.3), FPGA_U1_Auto (U1.D17)
D_IN: ChassisTimingInterface3 (U13.28), FPGA_U1_Auto (U1.N10)
DONE: ChassisTimingInterface3 (Q3.1 R31.2 U13.13), FPGA_U1_Auto (U1.V17)
FAIL: ChassisTimingInterface1 (Q1.1 R4.2), FPGA_U1_Auto (U1.R9)
HSWAP: ChassisTimingInterface3 (R35.1), FPGA_U1_Auto (U1.B3)
INIT_B: ChassisTimingInterface3 (R32.3 U13.11), FPGA_U1_Auto (U1.T3)
LED: ChassisTimingInterface2 (Q2.1), FPGA_U1_Auto (U1.A6)
LOS: ChassisTimingInterface2 (J1.8 R6.1), FPGA_U1_Auto (U1.A8)
M0: ChassisTimingInterface3 (R34.4), FPGA_U1_Auto (U1.M10)
M1: ChassisTimingInterface3 (R34.3), FPGA_U1_Auto (U1.V11)
M2: ChassisTimingInterface3 (R34.2), FPGA_U1_Auto (U1.T10)
OSCCLK_N: ChassisTimingInterface2 (U10.4), FPGA_U1_Auto (U1.A10)
OSCCLK_P: ChassisTimingInterface2 (U10.5), FPGA_U1_Auto (U1.B10)
PROG_B: ChassisTimingInterface3 (R32.1 S1.1 U13.6), FPGA_U1_Auto (U1.B1)
PWRSYNC_N: ChassisTimingInterface4 (U16.4), FPGA_U1_Auto (U1.U15)
PWRSYNC_P: ChassisTimingInterface4 (U16.3), FPGA_U1_Auto (U1.V15)
S1_16.S1_N: ChassisTimingInterface1 (P1.12), FPGA_U1_Auto (U1.D9)
S1_16.S1_P: ChassisTimingInterface1 (P1.10), FPGA_U1_Auto (U1.C9)
S1_16.S2_N: ChassisTimingInterface1 (P1.14), FPGA_U1_Auto (U1.D2)
S1_16.S2_P: ChassisTimingInterface1 (P1.16), FPGA_U1_Auto (U1.D1)
S1_16.S3_N: ChassisTimingInterface1 (P1.20), FPGA_U1_Auto (U1.E1)
S1_16.S3_P: ChassisTimingInterface1 (P1.18), FPGA_U1_Auto (U1.E2)
S1_16.S4_N: ChassisTimingInterface1 (P1.22), FPGA_U1_Auto (U1.F2)
S1_16.S4_P: ChassisTimingInterface1 (P1.24), FPGA_U1_Auto (U1.F1)
S1_16.S5_N: ChassisTimingInterface1 (P1.28), FPGA_U1_Auto (U1.H1)
S1_16.S5_P: ChassisTimingInterface1 (P1.26), FPGA_U1_Auto (U1.H2)
S1_16.S6_N: ChassisTimingInterface1 (P1.30), FPGA_U1_Auto (U1.H5)
S1_16.S6_P: ChassisTimingInterface1 (P1.32), FPGA_U1_Auto (U1.H6)
S1_16.S7_N: ChassisTimingInterface1 (P1.36), FPGA_U1_Auto (U1.L2)
S1_16.S7_P: ChassisTimingInterface1 (P1.34), FPGA_U1_Auto (U1.L1)
S1_16.S8_N: ChassisTimingInterface1 (P1.38), FPGA_U1_Auto (U1.K4)
S1_16.S8_P: ChassisTimingInterface1 (P1.40), FPGA_U1_Auto (U1.K3)
S1_16.S9_N: ChassisTimingInterface1 (P1.44), FPGA_U1_Auto (U1.K5)
S1_16.S9_P: ChassisTimingInterface1 (P1.42), FPGA_U1_Auto (U1.K6)
S10_N: ChassisTimingInterface1 (P1.46), FPGA_U1_Auto (U1.P1)
S10_P: ChassisTimingInterface1 (P1.48), FPGA_U1_Auto (U1.P2)
S11_N: ChassisTimingInterface1 (P1.52), FPGA_U1_Auto (U1.R2)
S11_P: ChassisTimingInterface1 (P1.50), FPGA_U1_Auto (U1.R3)
S12_N: ChassisTimingInterface1 (P1.54), FPGA_U1_Auto (U1.T1)
S12_P: ChassisTimingInterface1 (P1.56), FPGA_U1_Auto (U1.T2)
S13_N: ChassisTimingInterface1 (P1.60), FPGA_U1_Auto (U1.P4)
S13_P: ChassisTimingInterface1 (P1.58), FPGA_U1_Auto (U1.P3)
S14_N: ChassisTimingInterface1 (P1.62), FPGA_U1_Auto (U1.P7)
S14_P: ChassisTimingInterface1 (P1.64), FPGA_U1_Auto (U1.N7)
S15_N: ChassisTimingInterface1 (P1.68), FPGA_U1_Auto (U1.V6)
S15_P: ChassisTimingInterface1 (P1.66), FPGA_U1_Auto (U1.V5)
S16_N: ChassisTimingInterface1 (P1.70), FPGA_U1_Auto (U1.V9)
S16_P: ChassisTimingInterface1 (P1.72), FPGA_U1_Auto (U1.U9)
S17_32.S17_N: ChassisTimingInterface1 (P1.11), FPGA_U1_Auto (U1.D7)
S17_32.S17_P: ChassisTimingInterface1 (P1.9), FPGA_U1_Auto (U1.C7)
S17_32.S18_N: ChassisTimingInterface1 (P1.13), FPGA_U1_Auto (U1.E3)
S17_32.S18_P: ChassisTimingInterface1 (P1.15), FPGA_U1_Auto (U1.E4)
S17_32.S19_N: ChassisTimingInterface1 (P1.19), FPGA_U1_Auto (U1.E7)
S17_32.S19_P: ChassisTimingInterface1 (P1.17), FPGA_U1_Auto (U1.F7)
S17_32.S20_N: ChassisTimingInterface1 (P1.21), FPGA_U1_Auto (U1.G4)
S17_32.S20_P: ChassisTimingInterface1 (P1.23), FPGA_U1_Auto (U1.G3)
S17_32.S21_N: ChassisTimingInterface1 (P1.27), FPGA_U1_Auto (U1.G5)
S17_32.S21_P: ChassisTimingInterface1 (P1.25), FPGA_U1_Auto (U1.G6)
S17_32.S22_N: ChassisTimingInterface1 (P1.29), FPGA_U1_Auto (U1.H3)
S17_32.S22_P: ChassisTimingInterface1 (P1.31), FPGA_U1_Auto (U1.H4)
S17_32.S23_N: ChassisTimingInterface1 (P1.35), FPGA_U1_Auto (U1.L5)
S17_32.S23_P: ChassisTimingInterface1 (P1.33), FPGA_U1_Auto (U1.L6)
S17_32.S24_N: ChassisTimingInterface1 (P1.37), FPGA_U1_Auto (U1.J4)
S17_32.S24_P: ChassisTimingInterface1 (P1.39), FPGA_U1_Auto (U1.J5)
S17_32.S25_N: ChassisTimingInterface1 (P1.43), FPGA_U1_Auto (U1.J2)
S17_32.S25_P: ChassisTimingInterface1 (P1.41), FPGA_U1_Auto (U1.J1)
S17_32.S26_N: ChassisTimingInterface1 (P1.45), FPGA_U1_Auto (U1.L4)
S17_32.S26_P: ChassisTimingInterface1 (P1.47), FPGA_U1_Auto (U1.L3)
S17_32.S27_N: ChassisTimingInterface1 (P1.51), FPGA_U1_Auto (U1.M3)
S17_32.S27_P: ChassisTimingInterface1 (P1.49), FPGA_U1_Auto (U1.M4)
S17_32.S28_N: ChassisTimingInterface1 (P1.53), FPGA_U1_Auto (U1.M6)
S17_32.S28_P: ChassisTimingInterface1 (P1.55), FPGA_U1_Auto (U1.M5)
S17_32.S29_N: ChassisTimingInterface1 (P1.59), FPGA_U1_Auto (U1.N5)
S17_32.S29_P: ChassisTimingInterface1 (P1.57), FPGA_U1_Auto (U1.N4)
S17_32.S30_N: ChassisTimingInterface1 (P1.61), FPGA_U1_Auto (U1.P6)
S17_32.S30_P: ChassisTimingInterface1 (P1.63), FPGA_U1_Auto (U1.R6)
S17_32.S31_N: ChassisTimingInterface1 (P1.67), FPGA_U1_Auto (U1.T8)
S17_32.S31_P: ChassisTimingInterface1 (P1.65), FPGA_U1_Auto (U1.R8)
S17_32.S32_N: ChassisTimingInterface1 (P1.69), FPGA_U1_Auto (U1.N8)
S17_32.S32_P: ChassisTimingInterface1 (P1.71), FPGA_U1_Auto (U1.P8)
S33_48.S33_N: ChassisTimingInterface1 (P2.11), FPGA_U1_Auto (U1.E10)
S33_48.S33_P: ChassisTimingInterface1 (P2.9), FPGA_U1_Auto (U1.D10)
S33_48.S34_N: ChassisTimingInterface1 (P2.13), FPGA_U1_Auto (U1.F17)
S33_48.S34_P: ChassisTimingInterface1 (P2.15), FPGA_U1_Auto (U1.F18)
S33_48.S35_N: ChassisTimingInterface1 (P2.19), FPGA_U1_Auto (U1.F11)
S33_48.S35_P: ChassisTimingInterface1 (P2.17), FPGA_U1_Auto (U1.E11)
S33_48.S36_N: ChassisTimingInterface1 (P2.21), FPGA_U1_Auto (U1.H17)
S33_48.S36_P: ChassisTimingInterface1 (P2.23), FPGA_U1_Auto (U1.H16)
S33_48.S37_N: ChassisTimingInterface1 (P2.27), FPGA_U1_Auto (U1.J13)
S33_48.S37_P: ChassisTimingInterface1 (P2.25), FPGA_U1_Auto (U1.J12)
S33_48.S38_N: ChassisTimingInterface1 (P2.29), FPGA_U1_Auto (U1.L15)
S33_48.S38_P: ChassisTimingInterface1 (P2.31), FPGA_U1_Auto (U1.L16)
S33_48.S39_N: ChassisTimingInterface1 (P2.35), FPGA_U1_Auto (U1.L17)
S33_48.S39_P: ChassisTimingInterface1 (P2.33), FPGA_U1_Auto (U1.L18)
S33_48.S40_N: ChassisTimingInterface1 (P2.37), FPGA_U1_Auto (U1.J16)
S33_48.S40_P: ChassisTimingInterface1 (P2.39), FPGA_U1_Auto (U1.J17)
S33_48.S41_N: ChassisTimingInterface1 (P2.43), FPGA_U1_Auto (U1.J14)
S33_48.S41_P: ChassisTimingInterface1 (P2.41), FPGA_U1_Auto (U1.J15)
S33_48.S42_N: ChassisTimingInterface1 (P2.45), FPGA_U1_Auto (U1.M18)
S33_48.S42_P: ChassisTimingInterface1 (P2.47), FPGA_U1_Auto (U1.N18)
S33_48.S43_N: ChassisTimingInterface1 (P2.51), FPGA_U1_Auto (U1.N11)
S33_48.S43_P: ChassisTimingInterface1 (P2.49), FPGA_U1_Auto (U1.P11)
S33_48.S44_N: ChassisTimingInterface1 (P2.53), FPGA_U1_Auto (U1.P18)
S33_48.S44_P: ChassisTimingInterface1 (P2.55), FPGA_U1_Auto (U1.P17)
S33_48.S45_N: ChassisTimingInterface1 (P2.59), FPGA_U1_Auto (U1.T18)
S33_48.S45_P: ChassisTimingInterface1 (P2.57), FPGA_U1_Auto (U1.R18)
S33_48.S46_N: ChassisTimingInterface1 (P2.61), FPGA_U1_Auto (U1.T17)
S33_48.S46_P: ChassisTimingInterface1 (P2.63), FPGA_U1_Auto (U1.U18)
S33_48.S47_N: ChassisTimingInterface1 (P2.67), FPGA_U1_Auto (U1.R16)
S33_48.S47_P: ChassisTimingInterface1 (P2.65), FPGA_U1_Auto (U1.R15)
S33_48.S48_N: ChassisTimingInterface1 (P2.69), FPGA_U1_Auto (U1.P10)
S33_48.S48_P: ChassisTimingInterface1 (P2.71), FPGA_U1_Auto (U1.R10)
S49_64.S49_N: ChassisTimingInterface1 (P2.12), FPGA_U1_Auto (U1.D11)
S49_64.S49_P: ChassisTimingInterface1 (P2.10), FPGA_U1_Auto (U1.C11)
S49_64.S50_N: ChassisTimingInterface1 (P2.14), FPGA_U1_Auto (U1.F8)
S49_64.S50_P: ChassisTimingInterface1 (P2.16), FPGA_U1_Auto (U1.E8)
S49_64.S51_N: ChassisTimingInterface1 (P2.20), FPGA_U1_Auto (U1.C14)
S49_64.S51_P: ChassisTimingInterface1 (P2.18), FPGA_U1_Auto (U1.D14)
S49_64.S52_N: ChassisTimingInterface1 (P2.22), FPGA_U1_Auto (U1.E12)
S49_64.S52_P: ChassisTimingInterface1 (P2.24), FPGA_U1_Auto (U1.F12)
S49_64.S53_N: ChassisTimingInterface1 (P2.28), FPGA_U1_Auto (U1.F9)
S49_64.S53_P: ChassisTimingInterface1 (P2.26), FPGA_U1_Auto (U1.E9)
S49_64.S54_N: ChassisTimingInterface1 (P2.30), FPGA_U1_Auto (U1.G13)
S49_64.S54_P: ChassisTimingInterface1 (P2.32), FPGA_U1_Auto (U1.G14)
S49_64.S55_N: ChassisTimingInterface1 (P2.36), FPGA_U1_Auto (U1.H15)
S49_64.S55_P: ChassisTimingInterface1 (P2.34), FPGA_U1_Auto (U1.H14)
S49_64.S56_N: ChassisTimingInterface1 (P2.38), FPGA_U1_Auto (U1.K12)
S49_64.S56_P: ChassisTimingInterface1 (P2.40), FPGA_U1_Auto (U1.K13)
S49_64.S57_N: ChassisTimingInterface1 (P2.44), FPGA_U1_Auto (U1.K14)
S49_64.S57_P: ChassisTimingInterface1 (P2.42), FPGA_U1_Auto (U1.K15)
S49_64.S58_N: ChassisTimingInterface1 (P2.46), FPGA_U1_Auto (U1.B13)
S49_64.S58_P: ChassisTimingInterface1 (P2.48), FPGA_U1_Auto (U1.A13)
S49_64.S59_N: ChassisTimingInterface1 (P2.52), FPGA_U1_Auto (U1.M16)
S49_64.S59_P: ChassisTimingInterface1 (P2.50), FPGA_U1_Auto (U1.M15)
S49_64.S60_N: ChassisTimingInterface1 (P2.54), FPGA_U1_Auto (U1.M13)
S49_64.S60_P: ChassisTimingInterface1 (P2.56), FPGA_U1_Auto (U1.M14)
S49_64.S61_N: ChassisTimingInterface1 (P2.60), FPGA_U1_Auto (U1.N14)
S49_64.S61_P: ChassisTimingInterface1 (P2.58), FPGA_U1_Auto (U1.N15)
S49_64.S62_N: ChassisTimingInterface1 (P2.62), FPGA_U1_Auto (U1.P12)
S49_64.S62_P: ChassisTimingInterface1 (P2.64), FPGA_U1_Auto (U1.N12)
S49_64.S63_N: ChassisTimingInterface1 (P2.68), FPGA_U1_Auto (U1.R13)
S49_64.S63_P: ChassisTimingInterface1 (P2.66), FPGA_U1_Auto (U1.P13)
S49_64.S64_N: ChassisTimingInterface1 (P2.70), FPGA_U1_Auto (U1.R14)
S49_64.S64_P: ChassisTimingInterface1 (P2.72), FPGA_U1_Auto (U1.T14)
STCK: ChassisTimingInterface3 (U14.17), FPGA_U1_Auto (U1.B8)
STDI: ChassisTimingInterface3 (U14.15), FPGA_U1_Auto (U1.C3)
STDO: ChassisTimingInterface3 (U14.4), FPGA_U1_Auto (U1.C1)
STMS: ChassisTimingInterface3 (U14.18), FPGA_U1_Auto (U1.C2)
SW1: ChassisTimingInterface3 (S2.1), FPGA_U1_Auto (U1.T16)
SW2: ChassisTimingInterface3 (S2.2), FPGA_U1_Auto (U1.T15)
SW3: ChassisTimingInterface3 (S2.3), FPGA_U1_Auto (U1.V14)
SW4: ChassisTimingInterface3 (S2.4), FPGA_U1_Auto (U1.U14)
SW5: ChassisTimingInterface3 (S2.5), FPGA_U1_Auto (U1.V13)
SW6: ChassisTimingInterface3 (S2.6), FPGA_U1_Auto (U1.R12)
SW7: ChassisTimingInterface3 (S2.7), FPGA_U1_Auto (U1.T12)
SW8: ChassisTimingInterface3 (S2.8), FPGA_U1_Auto (U1.V12)
SW9: ChassisTimingInterface1 (P1.6), FPGA_U1_Auto (U1.C4)
SW10: ChassisTimingInterface1 (P1.8), FPGA_U1_Auto (U1.D5)
SYNC_N: ChassisTimingInterface2 (U6.2), FPGA_U1_Auto (U1.C17)
SYNC_P: ChassisTimingInterface2 (U6.1), FPGA_U1_Auto (U1.C18)
SYNCIN_N: ChassisTimingInterface2 (U4.6), FPGA_U1_Auto (U1.A14)
SYNCIN_P: ChassisTimingInterface2 (U4.7), FPGA_U1_Auto (U1.B14)
SYNCLK_N: ChassisTimingInterface1 (P3.16), FPGA_U1_Auto (U1.M9)
SYNCLK_P: ChassisTimingInterface1 (P3.15), FPGA_U1_Auto (U1.N9)
SYNCOUT_N: ChassisTimingInterface2 (U8.3), FPGA_U1_Auto (U1.A16)
SYNCOUT_P: ChassisTimingInterface2 (U8.2), FPGA_U1_Auto (U1.B16)
TCK: ChassisTimingInterface1 (U2.3), ChassisTimingInterface3 (U13.20 U14.13), FPGA_U1_Auto (U1.A17)
TDI_A: ChassisTimingInterface1 (P1.3 R1.2), ChassisTimingInterface3 (U13.22)
TDI_B: ChassisTimingInterface1 (P1.4 R1.1), FPGA_U1_Auto (U1.A2)
TDO: ChassisTimingInterface3 (U14.8), FPGA_U1_Auto (U1.C16)
TMS: ChassisTimingInterface1 (U2.1), ChassisTimingInterface3 (U13.21 U14.14), FPGA_U1_Auto (U1.D15)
